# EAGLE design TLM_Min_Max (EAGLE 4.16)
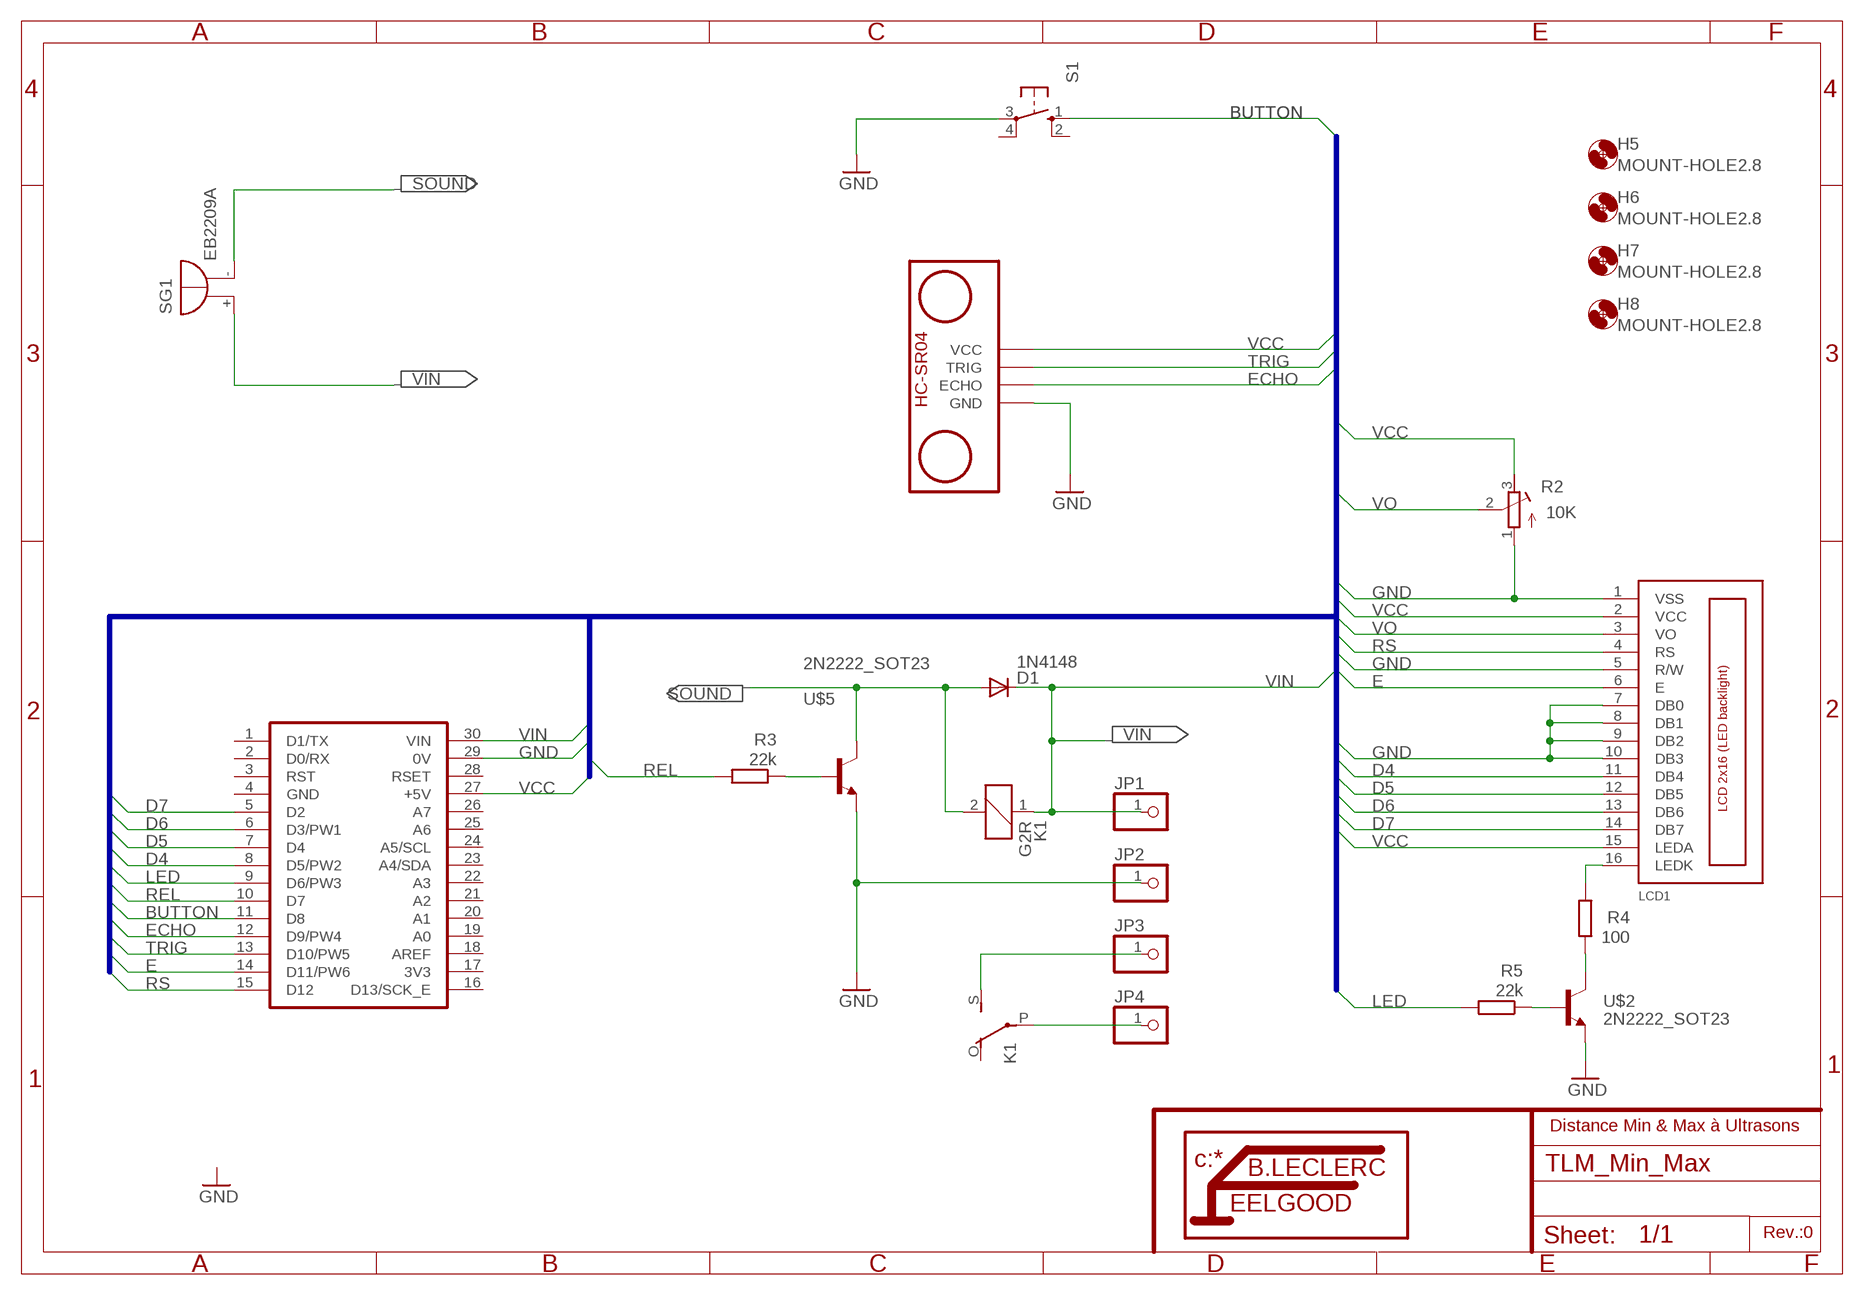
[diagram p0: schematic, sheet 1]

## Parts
D1  1N4148  DIODE-SOD106A-R  [SOD106A-R]
H5  MOUNT-HOLE2.8  [2,8]
H6  MOUNT-HOLE2.8  [2,8]
H7  MOUNT-HOLE2.8  [2,8]
H8  MOUNT-HOLE2.8  [2,8]
JP1  PINHD-1X1  [1X01]
JP2  PINHD-1X1  [1X01]
JP3  PINHD-1X1  [1X01]
JP4  PINHD-1X1  [1X01]
K1  G2R  [G2R]
LCD1  LCD_2X16_SIL  [HY-1602F]
R2  10K  R-TRIMM3103  [RTRIM3103]
R3  22k  R-EU_M1206  [M1206]
R4  100  R-EU_M1206  [M1206]
R5  22k  R-EU_M1206  [M1206]
S1  10-XX  [B3F-10XX]
SG1  EB2209A  [EB2209A]
U1  NANO  [NANO]
U$2  2N2222_SOT23  [SOT23-BEC]
U$3  HC-SR04  [HC-SR04]
U$5  2N2222_SOT23  [SOT23-BEC]

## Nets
BUTTON: S1.1(S) U1.11(D8)
D4: LCD1.11(DB4) U1.8(D5/PW2)
D5: LCD1.12(DB5) U1.7(D4)
D6: LCD1.13(DB6) U1.6(D3/PW1)
D7: LCD1.14(DB7) U1.5(D2)
E: LCD1.6(E) U1.14(D11/PW6)
ECHO: U1.12(D9/PW4) U$3.ECHO
GND: JP2.1 LCD1.1(VSS) LCD1.5(R/W) LCD1.7(DB0) LCD1.8(DB1) LCD1.9(DB2) LCD1.10(DB3) R2.1(E) S1.3(P) U1.29(0V) U$2.E U$3.GND U$5.E
LED: R5.2 U1.9(D6/PW3)
N$1: R3.1 U$5.B
N$3: LCD1.16(LEDK) R4.2
N$4: JP4.1 K1.P(2:P)
N$5: JP3.1 K1.S(2:S)
N$8: R4.1 U$2.C
N$9: R5.1 U$2.B
REL: R3.2 U1.10(D7)
RS: LCD1.4(RS) U1.15(D12)
SOUND: D1.A K1.2 SG1.- U$5.C
TRIG: U1.13(D10/PW5) U$3.TRIG
VCC: LCD1.2(VCC) LCD1.15(LEDA) R2.3(A) U1.27(+5V) U$3.VCC
VIN: D1.C JP1.1 K1.1 SG1.+ U1.30(VIN)
VO: LCD1.3(VO) R2.2(S)
Unconnected: K1.O(2:O) S1.2(S1) S1.4(P1) U1.1(D1/TX) U1.2(D0/RX) U1.3(RST) U1.16(D13/SCK_E) U1.18(AREF) U1.19(A0) U1.20(A1) U1.21(A2) U1.22(A3) U1.23(A4/SDA) U1.24(A5/SCL) U1.25(A6) U1.26(A7) U1.28(RSET)

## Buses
B$1

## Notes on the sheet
- Distance Min & Max à Ultrasons
- Rev.:0

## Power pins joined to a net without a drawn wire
3V3: U1.17(3V3)
GND: U1.4(GND)

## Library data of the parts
D1 = diode:DIODE-: DIODE
H5-H8 = holes:MOUNT-HOLE: MOUNTING HOLE with drill center marker
JP1-JP4 = pinhead:PINHD-1X1: PIN HEADER
K1 = relay:G2R: RELAY 1 x switch, Omron
LCD1 = lcd_2x16_led_backlight:LCD_2X16_SIL
R2 = rcl:R-TRIMM: Trimm resistor
R3-R5 = rcl:R-EU_: RESISTOR, European symbol
S1 = switch-omron:10-XX: OMRON SWITCH
SG1 = buzzer:EB2209A: BUZZER
U1 = Arduino:NANO
U$2 U$5 = transistor:2N2222_SOT23
U$3 = Arduino:HC-SR04

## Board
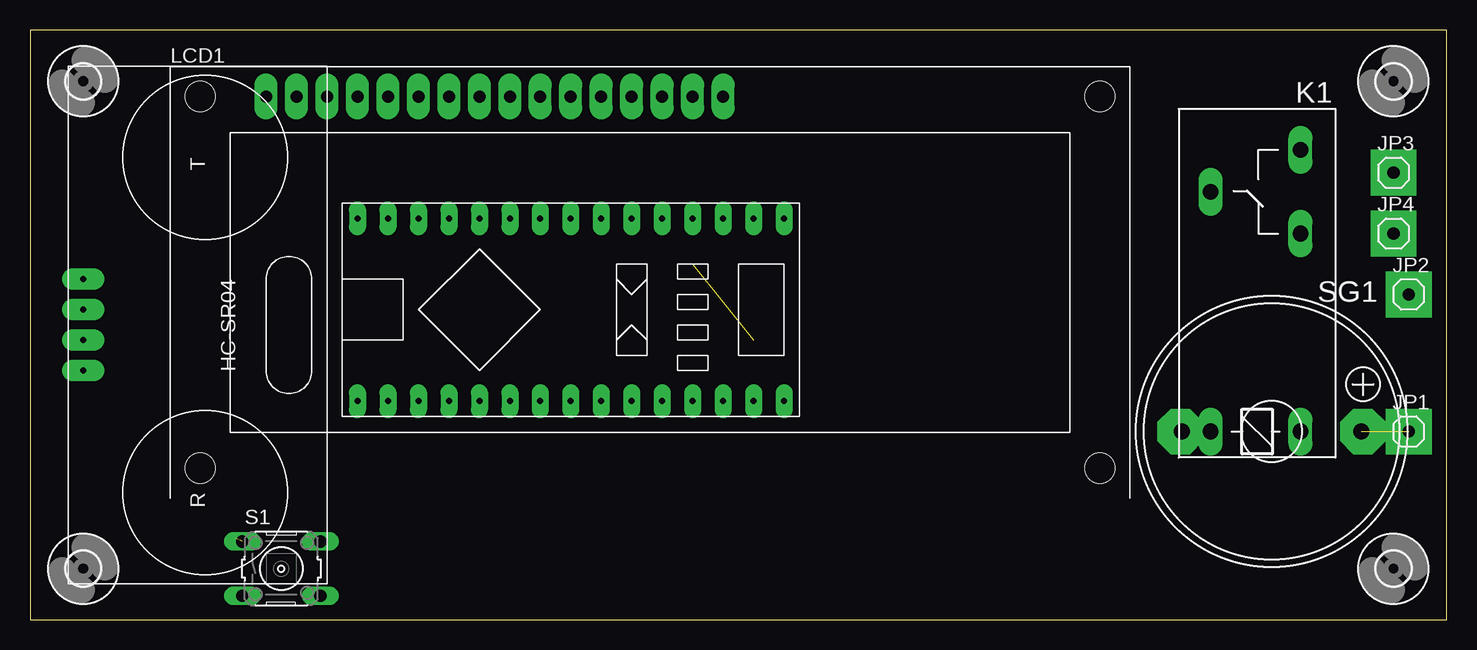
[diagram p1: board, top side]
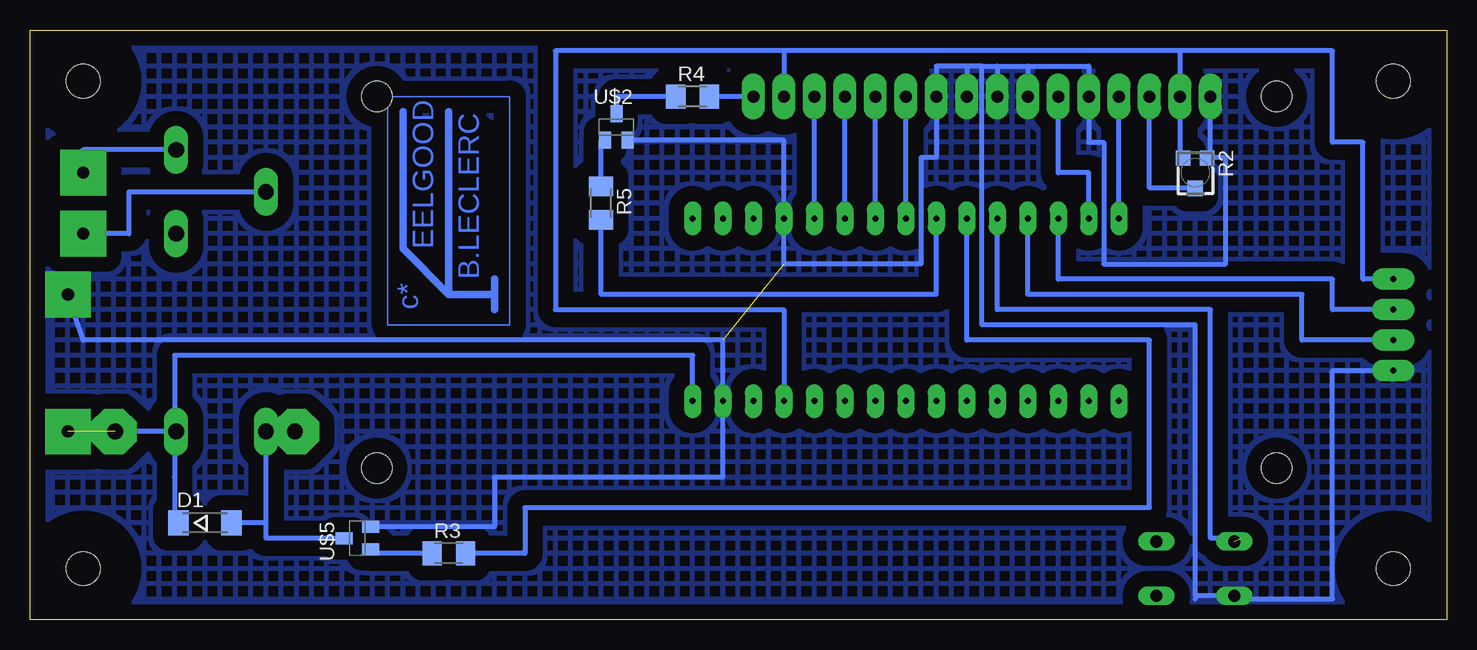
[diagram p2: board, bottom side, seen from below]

Size 118.09 x 49.2 mm. Coordinates in mm from the lower left corner, seen from the top.
Outline: 0,0 118.09,0 118.09,49.2 0,49.2 0,0
Copper layers (1*16): Top 0.035mm / dielectric 1.5mm / Bottom 0.035mm
Design rules "default": minimum track width 10mil, minimum drill 24mil, track to track 8mil, track to pad 8mil, pad to pad 8mil, via to via 8mil, smd to smd 8mil, copper to edge 40mil, drill to drill 8mil, minimum pad ring 10mil, minimum via ring 8mil, stop-mask expansion 4mil, vias tented up to drill 0mil, thermal gap 10mil

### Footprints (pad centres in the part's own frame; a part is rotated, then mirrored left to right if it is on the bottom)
SOD106A-R = smd 1.7 x 2.1: A 2.2,0; C -2.2,0
2,8 = hole 2.8: 0,0
1X01 = drill 1.016 octagon: 1 0,0
G2R = drill 1.321 long: 1 -2.54,-3.683; 2 -2.54,3.81; O 13.97,-3.683; P 17.45,3.81; S 20.955,-3.683
HY-1602F = drill 1 pad 1.93 long: 1 2.54,0; 2 5.08,0; 3 7.62,0; 4 10.16,0; 5 12.7,0; 6 15.24,0; 7 17.78,0; 8 20.32,0; 9 22.86,0; 10 25.4,0; 11 27.94,0; 12 30.48,0; 13 33.02,0; 14 35.56,0; 15 38.1,0; 16 40.64,0 | hole 2.5: -2.96,0; 72.04,0; -2.96,-31; 72.04,-31
RTRIM3103 = smd 1.2 x 1.25: 1 -1,-1.225; 3 1,-1.225 | smd 1.3 x 1.3: 2 0,1.3
M1206 = smd 1.6 x 2: 1 -1.4,0; 2 1.4,0
B3F-10XX = drill 1.016 long: 1 -3.251,2.261; 2 3.251,2.261; 3 -3.251,-2.261; 4 3.251,-2.261
EB2209A = drill 1.321 pad 2.54 octagon: + 7.493,0; - -7.493,0
NANO = drill 0.5 pad 1.422 long: 1 -7.62,17.78; 2 -7.62,15.24; 3 -7.62,12.7; 4 -7.62,10.16; 5 -7.62,7.62; 6 -7.62,5.08; 7 -7.62,2.54; 8 -7.62,0; 9 -7.62,-2.54; 10 -7.62,-5.08; 11 -7.62,-7.62; 12 -7.62,-10.16; 13 -7.62,-12.7; 14 -7.62,-15.24; 15 -7.62,-17.78; 16 7.62,-17.78; 17 7.62,-15.24; 18 7.62,-12.7; 19 7.62,-10.16; 20 7.62,-7.62; 21 7.62,-5.08; 22 7.62,-2.54; 23 7.62,0; 24 7.62,2.54; 25 7.62,5.08; 26 7.62,7.62; 27 7.62,10.16; 28 7.62,12.7; 29 7.62,15.24; 30 7.62,17.78
SOT23-BEC = smd 1 x 1.4: B -0.95,-1.1; C 0,1.1; E 0.95,-1.1
HC-SR04 = drill 0.5 pad 1.778 long: ECHO 1.27,-10.16; GND 3.81,-10.16; TRIG -1.27,-10.16; VCC -3.81,-10.16

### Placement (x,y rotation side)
D1  103.5,8.09 0 bottom
H5  113.66,4.28 0 top
H6  113.66,44.92 0 top
H7  4.44,4.28 0 top
H8  4.44,44.92 0 top
JP1  114.93,15.71 0 top
JP2  114.93,27.14 0 top
JP3  113.66,37.3 0 top
JP4  113.66,32.22 0 top
K1  102.23,18.25 90 top
LCD1  17.14,43.65 0 top
R2  20.95,37.3 180 bottom
R3  83.18,5.55 0 bottom
R4  62.86,43.65 0 bottom
R5  70.48,34.76 270 bottom
S1  20.95,4.28 0 top
SG1  103.5,15.71 0 top
U1  45.08,25.87 270 top
U$2  69.21,41.11 0 bottom
U$3  14.6,24.6 270 top
U$4  [LITTFEEL]  75.56,27.14 90 bottom
U$5  90.8,6.82 90 bottom

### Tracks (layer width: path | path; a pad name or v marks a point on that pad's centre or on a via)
BUTTON  (1 unrouted)
  Bottom 0.406: U1.11 37.46,25.87 19.68,25.87 19.68,6.82 17.14,6.82 18.41,6.82
D4
  Bottom 0.406: U1.8 LCD1.11
D5
  Bottom 0.406: U1.7 LCD1.12
D6
  Bottom 0.406: U1.6 LCD1.13
D7
  Bottom 0.406: U1.5 LCD1.14
E
  Bottom 0.406: LCD1.6 32.38,37.3 29.84,37.3 U1.14
ECHO
  Bottom 0.406: U1.12 34.92,27.14 12.06,27.14 12.06,23.33 U$3.ECHO
GND  (via drill 0.5 pad 1.27, 0.5 pad 3.81)  (1 unrouted)
  Bottom 0.406: R2.1 19.68,38.52 19.68,38.57 | U$2.E 55.24,40.01 U1.4 55.24,29.68 43.81,29.68 43.81,38.57 42.54,38.57 LCD1.10 42.54,46.19 40,46.19 | 34.92,46.19 29.84,46.19 LCD1.5 29.84,39.84 28.57,39.84 28.57,29.68 18.41,29.68 18.41,38.57 19.68,38.57 | 34.92,46.19 LCD1.7 | 37.46,46.19 34.92,46.19 | 38.73,46.19 37.46,46.19 | 38.73,46.19 40,46.19 | 37.46,46.19 LCD1.8 | 40,46.19 LCD1.9 | 18.41,2.02 S1.3 | 18.41,2.02 20.95,2.02 | 20.95,2.02 20.95,1.74 | 20.95,2.02 20.95,24.6 38.73,24.6 38.73,46.19 | U$3.GND 9.52,20.79 9.52,1.74 18.41,1.74 18.41,2.02 | U$5.E 79.37,7.77 79.37,11.9 60.32,11.9 U1.29 60.32,23.33 113.66,23.33 JP2.1 | 19.68,38.57 LCD1.1
  other vias: 114.93,27.14 19.68,43.65 29.84,43.65 34.92,43.65 37.46,43.65 40,43.65 42.54,43.65 17.77,1.99
  pour Bottom (isolate 1.27, no thermals, hatched): 0.63,48.73 117.47,48.73 117.47,47.46 117.47,0.47 0.63,0.47
LED
  Bottom 0.406: U1.9 42.54,27.14 70.48,27.14 R5.2 70.48,33.49
N$1
  Bottom 0.406: U$5.B 89.53,5.87 89.53,5.55 R3.1
N$3
  Bottom 0.406: 61.59,43.65 R4.2 LCD1.16
N$4
  Bottom 0.406: K1.P 109.85,35.7 109.85,32.22 JP4.1
N$5
  Bottom 0.406: K1.S 113.66,39.2 JP3.1
N$7  (via drill 0.5 pad 3.81)
  other vias: 113.66,37.3
N$8
  Bottom 0.406: R4.1 69.21,43.65 U$2.C
N$9
  Bottom 0.406: 70.48,36.03 R5.1 70.48,40.01 U$2.B
N$10  (via drill 0.5 pad 3.81)
  other vias: 113.66,32.22
N$12  (via drill 0.5 pad 1.27)
  other vias: 105.91,39.2
N$13  (via drill 0.5 pad 3.81)
  other vias: 114.93,15.71
N$14  (via drill 0.5 pad 1.27)
  other vias: 98.42,35.65
N$15  (via drill 0.5 pad 1.27)
  other vias: 105.91,32.22
N$16  (via drill 0.5 pad 1.27)
  other vias: 98.42,15.71
N$17  (via drill 0.5 pad 1.27)
  other vias: 105.91,15.71
N$19  (via drill 0.5 pad 1.27)
  other vias: 22.22,43.65
N$20  (via drill 0.5 pad 1.27)
  other vias: 24.76,43.65
N$21  (via drill 0.5 pad 1.27)
  other vias: 27.3,43.65
N$22  (via drill 0.5 pad 3.81)
  other vias: 95.88,15.71
N$23  (via drill 0.5 pad 1.27)
  other vias: 32.38,43.65
N$24  (via drill 0.5 pad 3.81)
  other vias: 111.12,15.71
N$28  (via drill 0.5 pad 1.27)
  other vias: 45.08,43.65
N$29  (via drill 0.5 pad 1.27)
  other vias: 47.62,43.65
N$30  (via drill 0.5 pad 1.27)
  other vias: 50.16,43.65
N$31  (via drill 0.5 pad 1.27)
  other vias: 52.7,43.65
N$32  (via drill 0.5 pad 1.27)
  other vias: 55.24,43.65
N$33  (via drill 0.5 pad 1.27)
  other vias: 57.78,43.65
N$35  (via drill 0.5 pad 1.27)
  other vias: 17.77,6.57
N$36  (via drill 0.5 pad 1.27)
  other vias: 24.25,1.99
N$37  (via drill 0.5 pad 1.27)
  other vias: 24.25,6.57
REL
  Bottom 0.406: U1.10 40,23.33 24.76,23.33 24.76,9.36 76.83,9.36 76.83,5.55 R3.2 81.91,5.55
RS
  Bottom 0.406: U1.15 LCD1.4
SOUND
  Bottom 0.406: 98.42,8.09 K1.2 SG1.- | 98.42,8.09 D1.A | U$5.C 98.42,6.82 98.42,8.09
TRIG
  Bottom 0.406: U1.13 32.38,28.41 9.52,28.41 9.52,25.87 U$3.TRIG
VCC
  Bottom 0.406: R2.3 22.22,38.52 LCD1.2 22.22,47.46 | U$3.VCC 6.98,28.41 6.98,39.84 9.52,39.84 9.52,47.46 22.22,47.46 | 55.24,47.46 LCD1.15 | 22.22,47.46 55.24,47.46 | U1.27 55.24,25.87 74.29,25.87 74.29,47.46 55.24,47.46
VIN  (1 unrouted)
  Bottom 0.406: U1.30 62.86,22.06 106.04,22.06 106.04,15.71 | D1.C 106.04,8.09 106.04,11.9 106.04,15.71 | 106.04,15.71 K1.1 | 106.04,15.71 SG1.+
VO
  Bottom 0.406: LCD1.3 24.76,36.03 20.95,36.03 R2.2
